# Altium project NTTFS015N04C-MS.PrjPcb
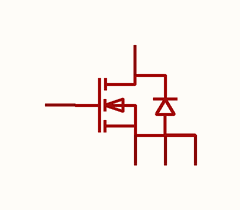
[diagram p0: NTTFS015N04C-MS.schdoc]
1 sheet, 1 parts. Net scope: global (net labels, ports and power ports of the same name join across sheets).

## Sheet NTTFS015N04C-MS.schdoc
size 127 x 101 mm

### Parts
Q?  nttfs015n04c-ms  [TDSON-8_L5.9-W5.2-P1.27-BL]  (value not drawn)

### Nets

Not connected (* = marked no-connect by the designer): Q? 1(S) 2(S) 3(S) 4(G) 5(D)

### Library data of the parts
Q? = nttfs015n04c-ms: 数量:1个N沟道;漏源电压(Vdss):40V;连续漏极电流(Id):50A;导通电阻(RDS(on)):14mΩ@10V;耗散功率(Pd):-;阈值电压(Vgs(th)):2.5V;; Manufacturer: MSKSEMI(美森科); AddInBom: yes; ModelId: ff3d8edf19694f3eb1c5df98919f3bc8; ModelTransform: 216.9287,242.5192,0,0,0,0,0,43.307,0; Number: 1个N沟道; Drain to Source Voltage: 40V; Current - Continuous Drain(Id): 50A; Gate Threshold Voltage (Vgs(th)): 2.5V; Gate Charge(Qg): 24nC@10V; Input Capacitance(Ciss): 1.54nF; Reverse Transfer Capacitance (Crss@Vds): 115pF; Type: N沟道; Output Capacitance(Coss): 171pF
